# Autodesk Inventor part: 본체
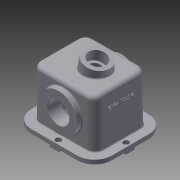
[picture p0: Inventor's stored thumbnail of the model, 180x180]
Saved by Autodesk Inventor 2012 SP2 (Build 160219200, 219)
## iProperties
Created: 2014-11
Part Number: 본체
Material: 알루미늄-6061
Document SubType Name: Modeling
Designer: cad-man
Density: 2.71 g/cm^3
Mass: 2852 g
Surface Area: 2105.51 cm^2
Volume: 1052.4 cm^3
Author: cad-man
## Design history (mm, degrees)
sketch "스케치2"
  geometry: L1 (-98, 87)-(98, 87); L2 (98, 87)-(98, -87); L3 (98, -87)-(-98, -87); L4 (-98, -87)-(-98, 87); 3 further points
  constraints: 8 end point, 2 midpoint, 2 parallel, 1 horizontal, 1 horizontal alignment, 1 perpendicular, 1 vertical alignment
  dimensions: "d0" = 196 distance of L2.end L3.end; "d1" = 174 distance of L1.end L2.end
extrude "돌출1" new body sketch "스케치2" distance "d2" = 10; taper "d3" = 0 deg
sketch "스케치3"
  geometry: L1 (-76, 65)-(76, 65); L2 (76, 65)-(76, -65); L3 (76, -65)-(-76, -65); L4 (-76, -65)-(-76, 65); 3 further points
  constraints: 8 end point, 2 midpoint, 2 parallel, 1 horizontal, 1 horizontal alignment, 1 perpendicular, 1 vertical alignment
  dimensions: "d4" = 152 distance of L2.end L3.end; "d5" = 130 distance of L3.end L1.start
extrude "돌출2" join sketch "스케치3" distance "d6" = 118; taper "d7" = 0 deg
sketch "스케치4"
  geometry: L1 (98, -87)-(98, 87) reference; L2 (98, 11)-(78, 11); L3 (78, 11)-(78, -11); L4 (78, -11)-(98, -11); L5 (98, -11)-(98, 11); 2 further points
  constraints: 8 end point, 2 parallel, 1 horizontal, 1 horizontal alignment, 1 midpoint, 1 perpendicular, 1 point on line
  dimensions: "d10" = 20 distance of L4.end L3.end; "d11" = 22 distance of L3.end L2.end
extrude "돌출3" join sketch "스케치4" distance "d12" = 5; taper "d13" = 0 deg
sketch "스케치12"
  geometry: 2 further points
  constraints: 1 horizontal alignment
  dimensions: "d60" = 88 distance of point (0, 0) point (-88, 0)
hole "구멍4" sketch "스케치12" at (-88, 0) diameter "d61" = 9; stored, may be unused: countersink angle "d65" = 90 deg, drill point angle "d67" = 118 deg; dims "d62" = 6, "d63" = 14, "d64" = 8.6, "d66" = 86
sketch "스케치5"
  geometry: L1 (-98, -87)-(98, -87) reference; L2 (-11, -87)-(11, -87); L3 (11, -87)-(11, -67); L4 (11, -67)-(-11, -67); L5 (-11, -67)-(-11, -87); 2 further points
  constraints: 8 end point, 2 parallel, 1 horizontal, 1 midpoint, 1 perpendicular, 1 point on line, 1 vertical alignment
  dimensions: "d14" = 22 distance of L4.end L3.end; "d15" = 20 distance of L3.end L2.end
extrude "돌출4" join sketch "스케치5" distance "d16" = 5; taper "d17" = 0 deg
sketch "스케치6"
  geometry: L1 (-11, 0)-(11, 0) reference; L2 (-76, 10)-(-76, 128) reference; L3 (76, 10)-(76, 128) reference; L4 (0, 68)-(-76, 68); L5 (0, 68)-(-17.88, 152.121); L6 (-17.88, 152.121)-(12.442, 158.566); L7 (12.442, 158.566)-(30.323, 74.445); L8 (30.323, 74.445)-(0, 68); 1 further point
  constraints: 10 end point, 2 parallel, 2 perpendicular, 1 point on line, 1 vertical alignment
  dimensions: "d18" = 68 distance from line of L1 L4.start; "d19" = 86 distance of L4.start L5.end; "d20" = 78 deg angle of L4 L5; "d21" = 62 diameter of L7 L5
revolve "회전1" sketch "스케치6" stored, may be unused: angle "d22" = 90 deg
sketch "스케치8"
  geometry: L1 (-66, 55)-(66, 55); L2 (66, 55)-(66, -55); L3 (66, -55)-(-66, -55); L4 (-66, -55)-(-66, 55); 3 further points
  constraints: 8 end point, 2 midpoint, 2 parallel, 1 horizontal, 1 horizontal alignment, 1 perpendicular, 1 vertical alignment
  dimensions: "d23" = 132 distance of L2.end L3.end; "d24" = 110 distance of L1.end L2.end
extrude "돌출5" cut sketch "스케치8" distance "d25" = 118; taper "d26" = 0 deg
sketch "스케치10"
  geometry: L1 (-65, 10)-(-65, 128) reference; L2 (55, 0)-(-55, 0) reference; L3 (0, 68)-(-65, 68); L4 (-65, 113.5)-(-77, 113.5); L5 (-77, 113.5)-(-77, 68); L6 (-77, 68)-(-65, 68); L7 (-55, 0)-(-55, 118) reference; L8 (-65, 113.5)-(-55, 113.5); L9 (-55, 113.5)-(-45, 103.5); L10 (-45, 103.5)-(-45, 68); 2 further points
  constraints: 14 end point, 4 point on line, 3 perpendicular, 2 horizontal, 1 collinear, 1 midpoint, 1 vertical alignment
  dimensions: "d27" = 68 distance between parallel lines of L2 L3; "d28" = 91 diameter of L4 L3; "d29" = 12 distance of L4.start L4.end; "d30" = 10 distance between parallel lines of L10 L7; "d31" = 45 deg angle of L7 L9
revolve "회전2" sketch "스케치10" stored, may be unused: angle "d32" = 90 deg
hole "구멍1" diameter "d35" = 52; stored, may be unused: countersink angle "d39" = 90 deg, drill point angle "d41" = 118 deg; dims "d33" = 10, "d34" = 10, "d36" = 6, "d37" = 42, "d38" = 25, "d40" = 32
hole "구멍2" diameter "d44" = 52; stored, may be unused: countersink angle "d48" = 90 deg, drill point angle "d50" = 118 deg; dims "d42" = 10, "d43" = 10, "d45" = 6, "d46" = 42, "d47" = 25, "d49" = 32
hole "구멍3" diameter "d53" = 30; stored, may be unused: countersink angle "d57" = 90 deg, drill point angle "d59" = 118 deg; dims "d51" = 10, "d52" = 10, "d54" = 6, "d55" = 42, "d56" = 25, "d58" = 86
sketch "스케치13"
  geometry: L1 (-98, 87)-(98, 87) reference; L2 (98, -87)-(-98, -87) reference; C1 r 7 at (-88, 0) reference; 4 further points
  constraints: 2 vertical alignment, 1 horizontal alignment
  dimensions: "d68" = 176 distance of point (88, 0) C1.centre; "d69" = 10 distance from line of L1 point (0, 77); "d70" = 10 distance from line of L2 point (0, -77)
hole "구멍5" sketch "스케치13" at (88, 0), (0, 77), (0, -77) diameter "d71" = 9; stored, may be unused: countersink angle "d75" = 90 deg, drill point angle "d77" = 118 deg; dims "d72" = 6, "d73" = 14, "d74" = 8.6, "d76" = 86
sketch "스케치14"
  geometry: L1 (0, 152)-(0, -22) reference; 3 further points
  constraints: 1 horizontal alignment, 1 midpoint, 1 other
  dimensions: "d78" = 92 distance of point (10, 65) point (-82, 65)
feature "엠보싱1" sketch "스케치14" dims "d0" = 196, "d1" = 174, "d10" = 20, "d11" = 22, "d79" = 1, "d80" = 0
sketch "스케치15" dims "d81" = 70
  geometry: C1 r 26 at (0, 0) reference; C2 r 45.5 at (0, 0) reference; 3 further points
  constraints: 2 vertical alignment, 1 coincident, 2 other
hole "구멍6" sketch "스케치15" at (0, 35) diameter "d82" = 3.459; stored, may be unused: countersink angle "d86" = 90 deg, drill point angle "d88" = 118 deg; dims "d83" = 13, "d84" = 14, "d85" = 8.6, "d87" = 16
fillet "모깎기1" dims "d92" = 20
fillet "모깎기2" dims "d93" = 10
fillet "모깎기3" dims "d94" = 3, "d95" = 42
fillet "모깎기4" dims "d96" = 3
fillet "모깎기5" dims "d97" = 3
chamfer "모따기1" distance "d98" = 1; stored, may be unused: second distance "d99" = 2, angle "d100" = 45 deg
fillet "모깎기6" dims "d101" = 10
fillet "모깎기7" dims "d102" = 3
fillet "모깎기8" dims "d103" = 0.3
node "솔리드1"
mirror "대칭1"
mirror "대칭2"
mirror "대칭3"
pattern_circular "원형 패턴1" dims angle "d90" = 360 deg
mirror "대칭4"
